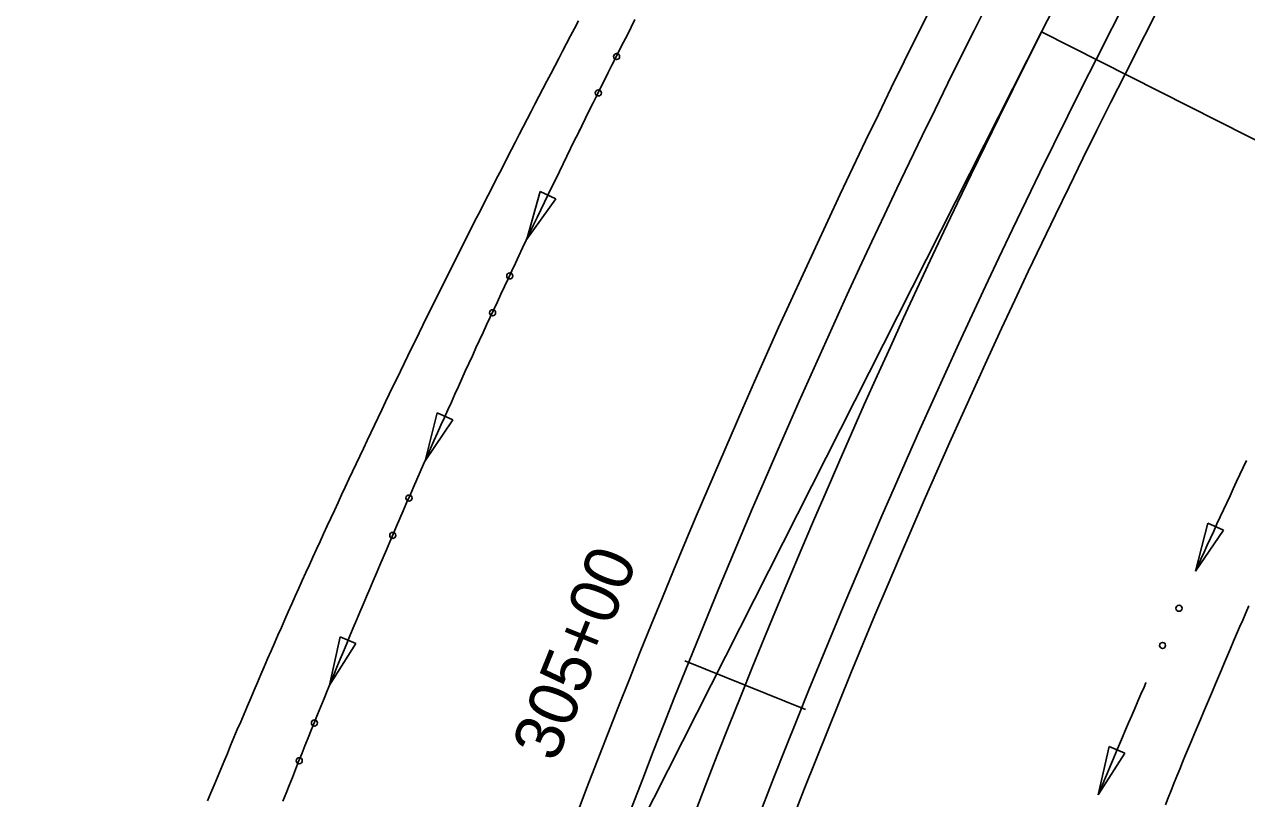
# Model space of a CAD drawing. Extents: x 1611108 to 1749517, y 619561 to 797725.
# Drawn here: x 1713104.8 to 1713255.2, y 759732.1 to 759827.4 of the extents above; entities that cross this region are included whole.
import ezdxf

# ---------------------------------------------------------------- set-up
doc = ezdxf.new("R2010")
doc.units = 0
for name, color, linetype in [('R_Ditch', 7, 'Continuous'), ('R_Horz Alg', 7, 'Continuous'), ('R_Horz Alg Annot', 7, 'Continuous'), ('R_Horz Alg Stationing', 7, 'Continuous'), ('R_Proposed Const Limits', 7, 'Continuous'), ('R_Proposed Road', 7, 'Continuous'), ('R_Proposed_SHLDR', 7, 'Continuous')]:
    doc.layers.add(name, color=color, linetype=linetype)

msp = doc.modelspace()

# ---------------------------------------------------------------- linework, layer by layer
at = {"layer": 'R_Ditch'}
for p, q in [((1713168.24, 759806.87), (1713166.6, 759801)), ((1713170.15, 759805.96), (1713168.24, 759806.87)), ((1713166.6, 759801), (1713170.15, 759805.96)), ((1713155.55, 759779.61), (1713154.07, 759773.7)), ((1713157.48, 759778.75), (1713155.55, 759779.61)), ((1713154.07, 759773.7), (1713157.48, 759778.75)), ((1713250.42, 759766.02), (1713248.89, 759760.12)), ((1713252.34, 759765.14), (1713250.42, 759766.02)), ((1713248.89, 759760.12), (1713252.34, 759765.14)), ((1713143.62, 759752.02), (1713142.31, 759746.07)), ((1713142.31, 759746.07), (1713145.57, 759751.21)), ((1713145.57, 759751.21), (1713143.62, 759752.02)), ((1713238.27, 759738.51), (1713236.91, 759732.57)), ((1713236.91, 759732.57), (1713240.22, 759737.69)), ((1713240.22, 759737.69), (1713238.27, 759738.51))]:
    msp.add_line(p, q, dxfattribs=at)
for points in [[(1713136.58, 759731.8), (1713136.97, 759732.77), (1713137.35, 759733.74), (1713137.74, 759734.72), (1713138.12, 759735.69), (1713138.51, 759736.66), (1713138.9, 759737.63), (1713139.29, 759738.6), (1713139.68, 759739.57), (1713140.07, 759740.54), (1713140.46, 759741.51), (1713140.85, 759742.48), (1713141.24, 759743.45), (1713141.64, 759744.42), (1713142.03, 759745.39), (1713142.43, 759746.36), (1713142.83, 759747.33), (1713143.23, 759748.29), (1713143.62, 759749.26), (1713144.02, 759750.23), (1713144.43, 759751.19), (1713144.83, 759752.16), (1713145.23, 759753.12), (1713145.63, 759754.09), (1713146.04, 759755.05), (1713146.44, 759756.02), (1713146.85, 759756.98), (1713147.26, 759757.94), (1713147.67, 759758.91), (1713148.08, 759759.87), (1713148.49, 759760.83), (1713148.9, 759761.79), (1713149.31, 759762.75), (1713149.72, 759763.71), (1713150.13, 759764.67), (1713150.55, 759765.63), (1713150.96, 759766.59), (1713151.38, 759767.55), (1713151.8, 759768.51), (1713152.22, 759769.47), (1713152.64, 759770.43), (1713153.06, 759771.38), (1713153.48, 759772.34), (1713153.9, 759773.3), (1713154.32, 759774.25), (1713154.75, 759775.21), (1713155.17, 759776.16), (1713155.6, 759777.12), (1713156.02, 759778.07), (1713156.45, 759779.03), (1713156.88, 759779.98), (1713157.31, 759780.93), (1713157.74, 759781.88), (1713158.17, 759782.84), (1713158.6, 759783.79), (1713159.03, 759784.74), (1713159.47, 759785.69), (1713159.9, 759786.64), (1713160.34, 759787.59), (1713160.77, 759788.54), (1713161.21, 759789.49), (1713161.65, 759790.44), (1713162.09, 759791.39), (1713162.53, 759792.33), (1713162.97, 759793.28), (1713163.41, 759794.23), (1713163.85, 759795.17), (1713164.3, 759796.12), (1713164.74, 759797.07), (1713165.19, 759798.01), (1713165.63, 759798.95), (1713166.08, 759799.9), (1713166.53, 759800.84), (1713166.98, 759801.79), (1713167.43, 759802.73), (1713167.88, 759803.67), (1713168.33, 759804.61), (1713168.78, 759805.55), (1713169.24, 759806.5), (1713169.69, 759807.44), (1713170.15, 759808.38), (1713170.6, 759809.32), (1713171.06, 759810.25), (1713171.52, 759811.19), (1713171.98, 759812.13), (1713172.44, 759813.07), (1713172.9, 759814.01), (1713173.36, 759814.94), (1713173.82, 759815.88), (1713174.28, 759816.82), (1713174.75, 759817.75), (1713175.21, 759818.69), (1713175.68, 759819.62), (1713176.15, 759820.55), (1713176.61, 759821.49), (1713177.08, 759822.42), (1713177.55, 759823.35), (1713178.02, 759824.29), (1713178.49, 759825.22), (1713178.97, 759826.15), (1713179.44, 759827.08), (1713179.91, 759828.01)], [(1713173.14, 759814.5), (1713172.9, 759814.01), (1713172.44, 759813.07), (1713171.98, 759812.13), (1713171.52, 759811.19), (1713171.06, 759810.25), (1713170.6, 759809.32), (1713170.15, 759808.38), (1713169.69, 759807.44), (1713169.24, 759806.5), (1713168.78, 759805.55), (1713168.33, 759804.61), (1713167.88, 759803.67), (1713167.43, 759802.73), (1713166.98, 759801.79), (1713166.61, 759801)], [(1713173.16, 759814.54), (1713173.14, 759814.5)], [(1713160.24, 759787.38), (1713159.9, 759786.64), (1713159.47, 759785.69), (1713159.03, 759784.74), (1713158.6, 759783.79), (1713158.17, 759782.84), (1713157.74, 759781.88), (1713157.31, 759780.93), (1713156.88, 759779.98), (1713156.45, 759779.03), (1713156.02, 759778.07), (1713155.6, 759777.12), (1713155.17, 759776.16), (1713154.75, 759775.21), (1713154.32, 759774.25), (1713154.08, 759773.7)], [(1713160.26, 759787.41), (1713160.24, 759787.38)], [(1713255.18, 759773.73), (1713255.18, 759773.72), (1713254.77, 759772.86), (1713254.36, 759771.99), (1713253.96, 759771.13), (1713253.55, 759770.26), (1713253.15, 759769.39), (1713252.75, 759768.53), (1713252.35, 759767.66), (1713251.94, 759766.79), (1713251.54, 759765.92), (1713251.14, 759765.05), (1713250.75, 759764.18), (1713250.35, 759763.32), (1713249.95, 759762.45), (1713249.55, 759761.57), (1713249.16, 759760.7), (1713248.89, 759760.12)], [(1713148.09, 759759.91), (1713148.08, 759759.87), (1713147.67, 759758.91), (1713147.26, 759757.94), (1713146.85, 759756.98), (1713146.44, 759756.02), (1713146.04, 759755.05), (1713145.63, 759754.09), (1713145.23, 759753.12), (1713144.83, 759752.16), (1713144.43, 759751.19), (1713144.02, 759750.23), (1713143.62, 759749.26), (1713143.23, 759748.29), (1713142.83, 759747.33), (1713142.43, 759746.36), (1713142.31, 759746.07)], [(1713148.11, 759759.94), (1713148.09, 759759.91)], [(1713242.79, 759746.37), (1713242.57, 759745.84), (1713242.19, 759744.97), (1713241.81, 759744.09), (1713241.43, 759743.21), (1713241.05, 759742.33), (1713240.67, 759741.45), (1713240.3, 759740.57), (1713239.92, 759739.69), (1713239.55, 759738.81), (1713239.17, 759737.93), (1713238.8, 759737.05), (1713238.43, 759736.17), (1713238.06, 759735.29), (1713237.69, 759734.41), (1713237.32, 759733.52), (1713236.95, 759732.64), (1713236.92, 759732.57)], [(1713242.81, 759746.41), (1713242.79, 759746.37)], [(1713136.72, 759732.15), (1713136.71, 759732.11)]]:
    msp.add_lwpolyline(points, dxfattribs=at)
for centre in [(1713177.65, 759823.47), (1713175.4, 759818.99), (1713164.5, 759796.46), (1713162.38, 759791.92), (1713152.1, 759769.1), (1713150.1, 759764.51), (1713246.87, 759755.54), (1713244.84, 759750.96), (1713140.46, 759741.42), (1713138.59, 759736.77)]:
    msp.add_circle(centre, 0.375, dxfattribs=at)
at = {"layer": 'R_Horz Alg'}
msp.add_line((1713229.96, 759826.5), (1713240.51, 759847.35), dxfattribs=at)
msp.add_arc((1714159.53, 759356.26), 1041.74, 153.16667, 180.59167, dxfattribs=at)
at = {"layer": 'R_Horz Alg Annot'}
msp.add_line((1713115.22, 759599.68), (1713229.96, 759826.5), dxfattribs=at)
msp.add_lwpolyline([(1713229.96, 759826.5), (1713345.97, 759767.81)], dxfattribs=at)
at = {"layer": 'R_Horz Alg Stationing'}
msp.add_lwpolyline([(1713186.05, 759749.05), (1713200.89, 759743.07)], dxfattribs=at)
at = {"layer": 'R_Proposed Const Limits'}
for points in [[(1713127.3, 759731.83), (1713127.71, 759732.81), (1713128.11, 759733.78), (1713128.52, 759734.76), (1713128.92, 759735.73), (1713129.33, 759736.71), (1713129.74, 759737.68), (1713130.14, 759738.65), (1713130.55, 759739.62), (1713130.96, 759740.6), (1713131.38, 759741.57), (1713131.79, 759742.54), (1713132.2, 759743.51), (1713132.62, 759744.48), (1713133.03, 759745.45), (1713133.45, 759746.42), (1713133.86, 759747.39), (1713134.28, 759748.35), (1713134.7, 759749.32), (1713135.12, 759750.29), (1713135.54, 759751.26), (1713135.96, 759752.22), (1713136.39, 759753.19), (1713136.81, 759754.16), (1713137.23, 759755.12), (1713137.66, 759756.08), (1713138.09, 759757.05), (1713138.53, 759758.01), (1713138.96, 759758.97), (1713139.4, 759759.93), (1713139.83, 759760.89), (1713140.27, 759761.85), (1713140.71, 759762.81), (1713141.15, 759763.77), (1713141.59, 759764.72), (1713142.03, 759765.68), (1713142.47, 759766.64), (1713142.91, 759767.59), (1713143.36, 759768.55), (1713143.8, 759769.51), (1713144.25, 759770.46), (1713144.69, 759771.42), (1713145.14, 759772.37), (1713145.59, 759773.32), (1713146.04, 759774.28), (1713146.49, 759775.23), (1713146.94, 759776.18), (1713147.39, 759777.13), (1713147.84, 759778.09), (1713148.3, 759779.04), (1713148.75, 759779.99), (1713149.21, 759780.94), (1713149.66, 759781.89), (1713150.12, 759782.83), (1713150.58, 759783.78), (1713151.04, 759784.73), (1713151.5, 759785.68), (1713151.96, 759786.63), (1713152.42, 759787.57), (1713152.88, 759788.52), (1713153.35, 759789.46), (1713153.81, 759790.41), (1713154.27, 759791.35), (1713154.74, 759792.3), (1713155.21, 759793.24), (1713155.68, 759794.18), (1713156.14, 759795.13), (1713156.61, 759796.07), (1713157.08, 759797.01), (1713157.56, 759797.95), (1713158.03, 759798.89), (1713158.5, 759799.83), (1713158.98, 759800.77), (1713159.45, 759801.71), (1713159.93, 759802.65), (1713160.4, 759803.59), (1713160.88, 759804.52), (1713161.36, 759805.46), (1713161.85, 759806.39), (1713162.32, 759807.33), (1713162.8, 759808.27), (1713163.28, 759809.2), (1713163.75, 759810.14), (1713164.23, 759811.08), (1713164.71, 759812.01), (1713165.19, 759812.95), (1713165.67, 759813.88), (1713166.15, 759814.82), (1713166.63, 759815.75), (1713167.12, 759816.69), (1713167.6, 759817.62), (1713168.08, 759818.55), (1713168.57, 759819.49), (1713169.05, 759820.42), (1713169.54, 759821.35), (1713170.03, 759822.28), (1713170.52, 759823.21), (1713171, 759824.14), (1713171.49, 759825.07), (1713171.99, 759826), (1713172.48, 759826.93), (1713172.97, 759827.86)], [(1713245.21, 759731.32), (1713245.55, 759732.21), (1713245.9, 759733.09), (1713246.25, 759733.97), (1713246.61, 759734.85), (1713246.96, 759735.73), (1713247.31, 759736.61), (1713247.66, 759737.49), (1713248.02, 759738.37), (1713248.4, 759739.24), (1713248.77, 759740.11), (1713249.15, 759740.98), (1713249.53, 759741.86), (1713249.9, 759742.73), (1713250.27, 759743.6), (1713250.64, 759744.48), (1713251, 759745.35), (1713251.37, 759746.23), (1713251.74, 759747.1), (1713252.11, 759747.98), (1713252.48, 759748.85), (1713252.85, 759749.72), (1713253.22, 759750.6), (1713253.59, 759751.47), (1713253.96, 759752.34), (1713254.33, 759753.21), (1713254.71, 759754.09), (1713255.08, 759754.96), (1713255.46, 759755.83)]]:
    msp.add_lwpolyline(points, dxfattribs=at)
at = {"layer": 'R_Proposed Road'}
msp.add_line((1713236.66, 759823.11), (1713247.2, 759843.96), dxfattribs=at)
for radius, end in [(1049.24, 178.28394), (1034.24, 180.59167)]:
    msp.add_arc((1714159.53, 759356.26), radius, 153.16667, end, dxfattribs=at)
at = {"layer": 'R_Proposed_SHLDR'}
msp.add_line((1713240.23, 759821.31), (1713250.77, 759842.16), dxfattribs=at)
for radius, end in [(1055.24, 178.28394), (1030.24, 180.59167)]:
    msp.add_arc((1714159.53, 759356.26), radius, 153.16667, end, dxfattribs=at)

# ---------------------------------------------------------------- texts
at = {"layer": 'R_Horz Alg Stationing'}
msp.add_text('305+00', height=6, rotation=68.0261, dxfattribs=at).set_placement((1713170.17, 759736.43))

doc.saveas('drawing.dxf')
